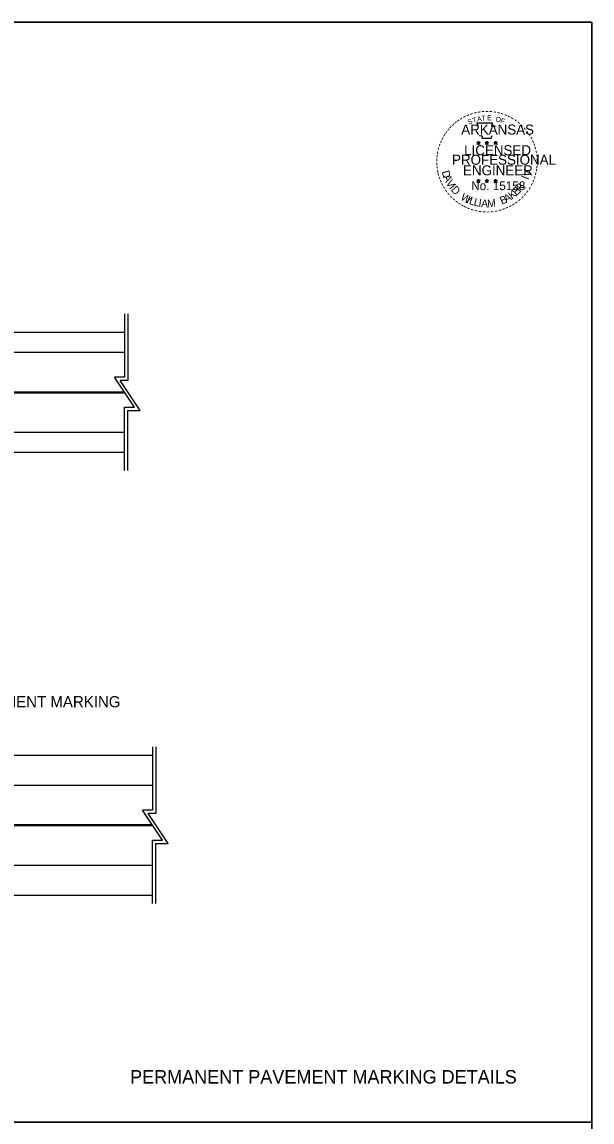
# Model space of a CAD drawing. Extents: x 1373096 to 1373266, y 381130 to 381790.
# Drawn here: x 1373208.9 to 1373266, y 381680.2 to 381790.2 of the extents above; entities that cross this region are included whole.
import ezdxf

# ---------------------------------------------------------------- set-up
doc = ezdxf.new("R2010")
doc.units = 0
for name, color, linetype in [('Default', 7, 'Continuous'), ('DSN_DRFT_Junk-No-Plot', 7, 'Continuous'), ('R_Border Notes', 7, 'Continuous'), ('R_Border PE', 7, 'Continuous'), ('R_Draft', 7, 'Continuous')]:
    doc.layers.add(name, color=color, linetype=linetype)

msp = doc.modelspace()

# ---------------------------------------------------------------- linework, layer by layer
at = {"layer": 'Default'}
for p, q in [((1373219.17, 381760.98), (1373219.17, 381754.65)), ((1373219.5, 381760.98), (1373219.5, 381754.31)), ((1373219.17, 381754.65), (1373218.17, 381754.65)), ((1373220.17, 381751.65), (1373218.17, 381754.65)), ((1373220.72, 381751.31), (1373218.72, 381754.31)), ((1373219.5, 381754.31), (1373218.72, 381754.31)), ((1373219.17, 381745.31), (1373219.17, 381751.65)), ((1373219.17, 381751.65), (1373220.17, 381751.65)), ((1373219.5, 381745.31), (1373219.5, 381751.31)), ((1373219.5, 381751.31), (1373220.72, 381751.31)), ((1373221.97, 381717.7), (1373221.97, 381711.36)), ((1373222.31, 381717.7), (1373222.31, 381711.03)), ((1373221.97, 381711.36), (1373220.97, 381711.36)), ((1373222.97, 381708.36), (1373220.97, 381711.36)), ((1373223.53, 381708.03), (1373221.53, 381711.03)), ((1373222.31, 381711.03), (1373221.53, 381711.03)), ((1373221.97, 381702.02), (1373221.97, 381708.36)), ((1373221.97, 381708.36), (1373222.97, 381708.36)), ((1373222.31, 381702.02), (1373222.31, 381708.03)), ((1373222.31, 381708.03), (1373223.53, 381708.03))]:
    msp.add_line(p, q, dxfattribs=at)
for points in [[(1373095.97, 381790.17), (1373095.97, 381680.17), (1373265.97, 381680.17), (1373265.97, 381790.17)], [(1373095.97, 381680.17), (1373095.97, 381570.17), (1373265.97, 381570.17), (1373265.97, 381680.17)], [(1373095.97, 381680.17), (1373095.97, 381570.17), (1373265.97, 381570.17), (1373265.97, 381680.17)]]:
    msp.add_lwpolyline(points, close=True, dxfattribs=at)
at = {"layer": 'DSN_DRFT_Junk-No-Plot'}
for points in [[(1373095.97, 381790.17), (1373265.97, 381790.17), (1373265.97, 381680.17), (1373095.97, 381680.17)], [(1373095.97, 381790.17), (1373095.97, 381680.17), (1373265.97, 381680.17), (1373265.97, 381790.17)], [(1373095.97, 381680.17), (1373265.97, 381680.17), (1373265.97, 381570.17), (1373095.97, 381570.17)], [(1373095.97, 381680.17), (1373095.97, 381570.17), (1373265.97, 381570.17), (1373265.97, 381680.17)]]:
    msp.add_lwpolyline(points, close=True, dxfattribs=at)
at = {"layer": 'R_Border PE'}
for p, q in [((1373254.43, 381778.13), (1373254.6, 381778.07)), ((1373254.43, 381778.13), (1373254.56, 381778.11)), ((1373254.43, 381778.13), (1373254.55, 381778.07)), ((1373254.6, 381778.26), (1373254.58, 381778.13)), ((1373254.6, 381778.07), (1373254.6, 381778.26)), ((1373254.6, 381778.26), (1373254.63, 381778.13)), ((1373254.78, 381778.13), (1373254.6, 381778.07)), ((1373254.78, 381778.13), (1373254.63, 381778.11)), ((1373254.78, 381778.13), (1373254.67, 381778.08)), ((1373255.26, 381778.13), (1373255.44, 381778.07)), ((1373255.26, 381778.13), (1373255.39, 381778.11)), ((1373255.26, 381778.13), (1373255.38, 381778.07)), ((1373255.44, 381778.26), (1373255.42, 381778.13)), ((1373255.44, 381778.07), (1373255.44, 381778.26)), ((1373255.44, 381778.26), (1373255.46, 381778.13)), ((1373255.61, 381778.13), (1373255.44, 381778.07)), ((1373255.61, 381778.13), (1373255.47, 381778.11)), ((1373255.61, 381778.13), (1373255.51, 381778.08)), ((1373256.15, 381778.12), (1373256.32, 381778.07)), ((1373256.15, 381778.12), (1373256.27, 381778.1)), ((1373256.15, 381778.12), (1373256.26, 381778.06)), ((1373256.32, 381778.25), (1373256.3, 381778.12)), ((1373256.32, 381778.07), (1373256.32, 381778.25)), ((1373256.32, 381778.25), (1373256.34, 381778.13)), ((1373256.49, 381778.12), (1373256.32, 381778.07)), ((1373256.49, 381778.12), (1373256.35, 381778.1)), ((1373256.49, 381778.12), (1373256.39, 381778.07)), ((1373254.5, 381777.93), (1373254.6, 381778.07)), ((1373254.5, 381777.93), (1373254.56, 381778.05)), ((1373254.5, 381777.93), (1373254.6, 381778.03)), ((1373254.71, 381777.93), (1373254.6, 381778.07)), ((1373254.71, 381777.93), (1373254.6, 381778.03)), ((1373254.71, 381777.93), (1373254.64, 381778.07)), ((1373255.33, 381777.93), (1373255.44, 381778.07)), ((1373255.33, 381777.93), (1373255.39, 381778.05)), ((1373255.33, 381777.93), (1373255.44, 381778.03)), ((1373255.54, 381777.93), (1373255.44, 381778.07)), ((1373255.54, 381777.93), (1373255.44, 381778.03)), ((1373255.54, 381777.93), (1373255.48, 381778.07)), ((1373256.21, 381777.92), (1373256.32, 381778.07)), ((1373256.21, 381777.92), (1373256.28, 381778.04)), ((1373256.21, 381777.92), (1373256.32, 381778.03)), ((1373256.43, 381777.92), (1373256.32, 381778.07)), ((1373256.43, 381777.92), (1373256.32, 381778.03)), ((1373256.43, 381777.92), (1373256.36, 381778.07)), ((1373254.43, 381774.34), (1373254.6, 381774.29)), ((1373254.43, 381774.34), (1373254.55, 381774.32)), ((1373254.43, 381774.34), (1373254.55, 381774.28)), ((1373254.49, 381774.14), (1373254.6, 381774.29)), ((1373254.49, 381774.14), (1373254.56, 381774.26)), ((1373254.49, 381774.14), (1373254.6, 381774.25)), ((1373254.6, 381774.47), (1373254.58, 381774.34)), ((1373254.6, 381774.29), (1373254.6, 381774.47)), ((1373254.6, 381774.47), (1373254.63, 381774.35)), ((1373254.77, 381774.34), (1373254.6, 381774.29)), ((1373254.71, 381774.14), (1373254.6, 381774.29)), ((1373254.71, 381774.14), (1373254.6, 381774.25)), ((1373254.77, 381774.34), (1373254.63, 381774.32)), ((1373254.71, 381774.14), (1373254.64, 381774.28)), ((1373254.77, 381774.34), (1373254.67, 381774.29)), ((1373255.26, 381774.34), (1373255.44, 381774.29)), ((1373255.26, 381774.34), (1373255.39, 381774.32)), ((1373255.26, 381774.34), (1373255.38, 381774.28)), ((1373255.33, 381774.14), (1373255.44, 381774.29)), ((1373255.33, 381774.14), (1373255.39, 381774.26)), ((1373255.33, 381774.14), (1373255.43, 381774.25)), ((1373255.44, 381774.47), (1373255.42, 381774.34)), ((1373255.54, 381774.14), (1373255.43, 381774.25)), ((1373255.44, 381774.29), (1373255.44, 381774.47)), ((1373255.44, 381774.47), (1373255.46, 381774.35)), ((1373255.61, 381774.34), (1373255.44, 381774.29)), ((1373255.54, 381774.14), (1373255.44, 381774.29)), ((1373255.61, 381774.34), (1373255.47, 381774.32)), ((1373255.54, 381774.14), (1373255.47, 381774.28)), ((1373255.61, 381774.34), (1373255.51, 381774.29)), ((1373256.14, 381774.34), (1373256.32, 381774.28)), ((1373256.14, 381774.34), (1373256.27, 381774.32)), ((1373256.14, 381774.34), (1373256.26, 381774.28)), ((1373256.21, 381774.13), (1373256.32, 381774.28)), ((1373256.21, 381774.13), (1373256.27, 381774.26)), ((1373256.21, 381774.13), (1373256.32, 381774.24)), ((1373256.32, 381774.47), (1373256.3, 381774.34)), ((1373256.32, 381774.28), (1373256.32, 381774.47)), ((1373256.32, 381774.47), (1373256.34, 381774.34)), ((1373256.49, 381774.34), (1373256.32, 381774.28)), ((1373256.43, 381774.13), (1373256.32, 381774.28)), ((1373256.43, 381774.13), (1373256.32, 381774.24)), ((1373256.49, 381774.34), (1373256.35, 381774.31)), ((1373256.43, 381774.13), (1373256.36, 381774.28)), ((1373256.49, 381774.34), (1373256.39, 381774.29))]:
    msp.add_line(p, q, dxfattribs=at)
for points in [[(1373254.45, 381780.07), (1373254.58, 381779.66)], [(1373256.2, 381779.61), (1373256.28, 381779.75), (1373255.93, 381779.74), (1373256.01, 381780.07), (1373254.45, 381780.07)], [(1373254.6, 381778.26), (1373254.71, 381777.93), (1373254.43, 381778.13), (1373254.78, 381778.13), (1373254.5, 381777.93), (1373254.6, 381778.26)], [(1373254.7, 381778.86), (1373254.7, 381778.81), (1373254.98, 381778.8), (1373254.95, 381778.57), (1373255.88, 381778.57), (1373255.99, 381778.84)], [(1373255.44, 381778.26), (1373255.54, 381777.93), (1373255.26, 381778.13), (1373255.61, 381778.13), (1373255.33, 381777.93), (1373255.44, 381778.26)], [(1373256.32, 381778.25), (1373256.43, 381777.92), (1373256.15, 381778.12), (1373256.49, 381778.12), (1373256.21, 381777.92), (1373256.32, 381778.25)], [(1373254.6, 381774.47), (1373254.71, 381774.14), (1373254.43, 381774.34), (1373254.77, 381774.34), (1373254.49, 381774.14), (1373254.6, 381774.47)], [(1373255.44, 381774.47), (1373255.54, 381774.14), (1373255.26, 381774.34), (1373255.61, 381774.34), (1373255.33, 381774.14), (1373255.44, 381774.47)], [(1373256.32, 381774.47), (1373256.43, 381774.13), (1373256.14, 381774.34), (1373256.49, 381774.34), (1373256.21, 381774.13), (1373256.32, 381774.47)]]:
    msp.add_lwpolyline(points, dxfattribs=at)
for centre, radius in [((1373254.6, 381778.07), 0.0861), ((1373254.6, 381778.07), 0.0723), ((1373254.6, 381778.07), 0.0579), ((1373254.6, 381778.07), 0.0495), ((1373254.6, 381778.07), 0.0374), ((1373255.44, 381778.07), 0.0861), ((1373255.44, 381778.07), 0.0723), ((1373255.44, 381778.07), 0.0579), ((1373255.44, 381778.07), 0.0495), ((1373255.44, 381778.07), 0.0374), ((1373256.32, 381778.07), 0.0861), ((1373256.32, 381778.07), 0.0723), ((1373256.32, 381778.07), 0.0579), ((1373256.32, 381778.07), 0.0495), ((1373256.32, 381778.07), 0.0374), ((1373254.6, 381778.07), 0.0248), ((1373254.6, 381778.07), 0.0148), ((1373255.44, 381778.07), 0.0248), ((1373255.44, 381778.07), 0.0148), ((1373256.32, 381778.07), 0.0248), ((1373256.32, 381778.07), 0.0148), ((1373254.6, 381774.29), 0.0861), ((1373254.6, 381774.29), 0.0723), ((1373254.6, 381774.29), 0.0579), ((1373254.6, 381774.29), 0.0495), ((1373254.6, 381774.29), 0.0374), ((1373254.6, 381774.29), 0.0248), ((1373254.6, 381774.29), 0.0148), ((1373255.44, 381774.29), 0.0861), ((1373255.44, 381774.29), 0.0723), ((1373255.44, 381774.29), 0.0579), ((1373255.44, 381774.29), 0.0495), ((1373255.44, 381774.29), 0.0374), ((1373255.44, 381774.29), 0.0248), ((1373255.44, 381774.29), 0.0148), ((1373256.32, 381774.28), 0.0861), ((1373256.32, 381774.28), 0.0723), ((1373256.32, 381774.28), 0.0579), ((1373256.32, 381774.28), 0.0495), ((1373256.32, 381774.28), 0.0374), ((1373256.32, 381774.28), 0.0248), ((1373256.32, 381774.28), 0.0148)]:
    msp.add_circle(centre, radius, dxfattribs=at)
at = {"layer": 'R_Draft'}
for p, q in [((1373142.78, 381759.15), (1373219.17, 381759.15)), ((1373142.78, 381757.15), (1373219.17, 381757.15)), ((1373142.74, 381753.2), (1373219.14, 381753.2)), ((1373142.81, 381753.1), (1373219.2, 381753.1)), ((1373142.78, 381749.15), (1373219.17, 381749.15)), ((1373142.78, 381747.15), (1373219.17, 381747.15)), ((1373145.58, 381716.86), (1373221.97, 381716.86)), ((1373145.58, 381713.86), (1373221.97, 381713.86)), ((1373145.55, 381709.91), (1373221.94, 381709.91)), ((1373145.62, 381709.81), (1373222.01, 381709.81)), ((1373145.58, 381705.86), (1373221.97, 381705.86)), ((1373145.58, 381702.86), (1373221.97, 381702.86))]:
    msp.add_line(p, q, dxfattribs=at)

# ---------------------------------------------------------------- texts
at = {"layer": 'Default'}
msp.add_text('6" DOUBLE YELLOW THERMOPLASTIC PAVEMENT MARKING', height=1.125, dxfattribs=at).set_placement((1373174.76, 381721.64))
at = {"layer": 'R_Border Notes'}
msp.add_text('PERMANENT PAVEMENT MARKING DETAILS', height=1.35, dxfattribs=at).set_placement((1373219.72, 381684.02))
at = {"layer": 'R_Border PE'}
for s, height, rotation, p in [('-', 0.8, 36.2317, (1373252.6, 381779.96)), ('-', 0.8, 34.0636, (1373252.89, 381780.15)), ('-', 0.8, 28.7918, (1373253.19, 381780.34)), ('-', 0.8, 24.3072, (1373253.51, 381780.5)), ('S', 0.5, 21.594, (1373253.63, 381779.91)), ('-', 0.8, 19.1761, (1373253.82, 381780.63)), ('T', 0.5, 16.4036, (1373254.08, 381780.07)), ('-', 0.8, 13.6302, (1373254.2, 381780.75)), ('A', 0.5, 11.2132, (1373254.5, 381780.2)), ('-', 0.8, 10.2193, (1373254.54, 381780.83)), ('T', 0.5, 6.0228, (1373254.92, 381780.28)), ('-', 0.8, 5.8968, (1373254.9, 381780.89)), ('-', 0.8, 0.1862, (1373255.29, 381780.92)), ('E', 0.5, 0.8323, (1373255.47, 381780.34)), ('-', 0.8, 357.743, (1373255.65, 381780.92)), ('-', 0.8, 352.1617, (1373256.02, 381780.89)), ('O', 0.5, 350.4515, (1373256.28, 381780.23)), ('-', 0.8, 347.2049, (1373256.38, 381780.83)), ('F', 0.5, 340.0707, (1373256.75, 381780.12)), ('-', 0.8, 342.3362, (1373256.7, 381780.76)), ('-', 0.8, 337.8551, (1373257.07, 381780.64)), ('-', 0.8, 334.1211, (1373257.38, 381780.51)), ('-', 0.8, 329.6409, (1373257.67, 381780.37)), ('-', 0.8, 325.8627, (1373257.99, 381780.19)), ('-', 0.8, 54.2325, (1373251.52, 381778.79)), ('-', 0.8, 50.6142, (1373251.72, 381779.08)), ('-', 0.8, 48.4231, (1373251.92, 381779.32)), ('-', 0.8, 42.9622, (1373252.15, 381779.56)), ('-', 0.8, 38.9507, (1373252.36, 381779.77)), ('-', 0.8, 320.5297, (1373258.3, 381779.97)), ('-', 0.8, 315.5786, (1373258.6, 381779.73)), ('-', 0.8, 309.8797, (1373258.88, 381779.45)), ('-', 0.8, 306.6522, (1373259.14, 381779.15)), ('-', 0.8, 67.7743, (1373251.07, 381777.92)), ('-', 0.8, 62.8713, (1373251.2, 381778.22)), ('-', 0.8, 58.0706, (1373251.35, 381778.53)), ('-', 0.7, 303.6753, (1373259.39, 381778.87)), ('-', 0.8, 299.6684, (1373259.55, 381778.57)), ('-', 0.8, 294.6628, (1373259.71, 381778.26)), ('-', 0.8, 81.2013, (1373250.79, 381776.89)), ('-', 0.8, 75.461, (1373250.86, 381777.25)), ('-', 0.8, 72.3945, (1373250.96, 381777.6)), ('-', 0.8, 290.5728, (1373259.84, 381777.97)), ('-', 0.8, 285.1233, (1373259.95, 381777.68)), ('-', 0.8, 280.5493, (1373260.05, 381777.31)), ('-', 0.8, 94.1959, (1373250.76, 381775.83)), ('-', 0.8, 89.0622, (1373250.74, 381776.19)), ('-', 0.8, 85.1863, (1373250.75, 381776.54)), ('-', 0.8, 276.5962, (1373260.13, 381776.93)), ('-', 0.8, 274.3301, (1373260.16, 381776.57)), ('-', 0.8, 269.9407, (1373260.18, 381776.25)), ('-', 0.8, 98.9479, (1373250.8, 381775.5)), ('-', 0.8, 101.7149, (1373250.86, 381775.13)), ('-', 0.8, 105.4578, (1373250.94, 381774.83)), ('D', 0.77, 286.2848, (1373250.91, 381775.2)), ('I', 0.77, 69.0301, (1373259.59, 381774.35)), ('V', 0.77, 72.6573, (1373259.7, 381774.62)), ('-', 0.8, 255.7626, (1373260.08, 381775.25)), ('-', 0.8, 260.9953, (1373260.14, 381775.59)), ('-', 0.8, 263.5172, (1373260.17, 381775.92)), ('-', 0.8, 109.0874, (1373251.05, 381774.52)), ('-', 0.8, 114.0643, (1373251.18, 381774.22)), ('-', 0.8, 115.7289, (1373251.33, 381773.91)), ('-', 0.8, 120.4471, (1373251.51, 381773.62)), ('A', 0.77, 292.7835, (1373251.05, 381774.7)), ('V', 0.77, 300.7936, (1373251.31, 381774.11)), ('I', 0.77, 308.3502, (1373251.63, 381773.59)), ('D', 0.77, 311.9774, (1373251.8, 381773.36)), ('E', 0.77, 44.0175, (1373258.4, 381772.75)), ('R', 0.77, 50.3651, (1373258.77, 381773.11)), (',', 0.77, 57.4684, (1373259.13, 381773.55)), ('-', 0.8, 244.6197, (1373259.75, 381774.24)), ('-', 0.8, 247.8887, (1373259.88, 381774.55)), ('-', 0.8, 252.8681, (1373259.99, 381774.89)), ('-', 0.8, 125.8934, (1373251.71, 381773.34)), ('-', 0.8, 130.7181, (1373251.94, 381773.06)), ('-', 0.8, 134.2238, (1373252.2, 381772.79)), ('W', 0.77, 328.0731, (1373252.74, 381772.47)), ('I', 0.77, 336.6877, (1373253.33, 381772.12)), ('L', 0.77, 340.3149, (1373253.6, 381772)), ('B', 0.77, 22.8589, (1373256.94, 381771.9)), ('A', 0.77, 28.9042, (1373257.39, 381772.09)), ('K', 0.77, 36.9143, (1373257.95, 381772.41)), ('-', 0.8, 225.7653, (1373258.9, 381772.97)), ('-', 0.8, 231.2538, (1373259.14, 381773.25)), ('-', 0.8, 233.8452, (1373259.35, 381773.54)), ('-', 0.8, 239.0712, (1373259.55, 381773.86)), ('-', 0.8, 138.9338, (1373252.46, 381772.56)), ('-', 0.8, 144.6463, (1373252.74, 381772.35)), ('-', 0.8, 148.0898, (1373253.02, 381772.17)), ('-', 0.8, 151.5704, (1373253.31, 381772.01)), ('-', 0.8, 154.6002, (1373253.57, 381771.88)), ('-', 0.8, 158.5612, (1373253.88, 381771.76)), ('L', 0.77, 346.6625, (1373254.08, 381771.83)), ('I', 0.77, 353.0101, (1373254.58, 381771.71)), ('A', 0.77, 356.6373, (1373254.86, 381771.66)), ('M', 0.77, 4.6473, (1373255.51, 381771.64)), ('-', 0.8, 199.4643, (1373257.19, 381771.82)), ('-', 0.8, 204.2516, (1373257.5, 381771.96)), ('-', 0.8, 207.3568, (1373257.81, 381772.12)), ('-', 0.8, 212.2491, (1373258.09, 381772.29)), ('-', 0.8, 215.7363, (1373258.36, 381772.48)), ('-', 0.8, 221.0851, (1373258.63, 381772.72)), ('-', 0.8, 162.7983, (1373254.23, 381771.65)), ('-', 0.8, 167.5555, (1373254.59, 381771.57)), ('-', 0.8, 173.1155, (1373254.97, 381771.51)), ('-', 0.8, 176.5183, (1373255.35, 381771.49)), ('-', 0.8, 181.5918, (1373255.72, 381771.49)), ('-', 0.8, 185.8167, (1373256.12, 381771.53)), ('-', 0.8, 191.2858, (1373256.49, 381771.6)), ('-', 0.8, 195.4743, (1373256.85, 381771.7))]:
    msp.add_text(s, height=height, rotation=rotation, dxfattribs=at).set_placement(p)
for s, height, p in [('ARKANSAS', 1, (1373252.88, 381778.92)), ('LICENSED', 1, (1373253.17, 381776.85)), ('PROFESSIONAL', 1, (1373251.96, 381775.9)), ('ENGINEER', 1, (1373253.06, 381774.84)), ('No. 15158', 0.878, (1373253.88, 381773.36)), ('AAMU', 0.00001, (1373255.4, 381771.63))]:
    msp.add_text(s, height=height, dxfattribs=at).set_placement(p)

doc.saveas('drawing.dxf')
